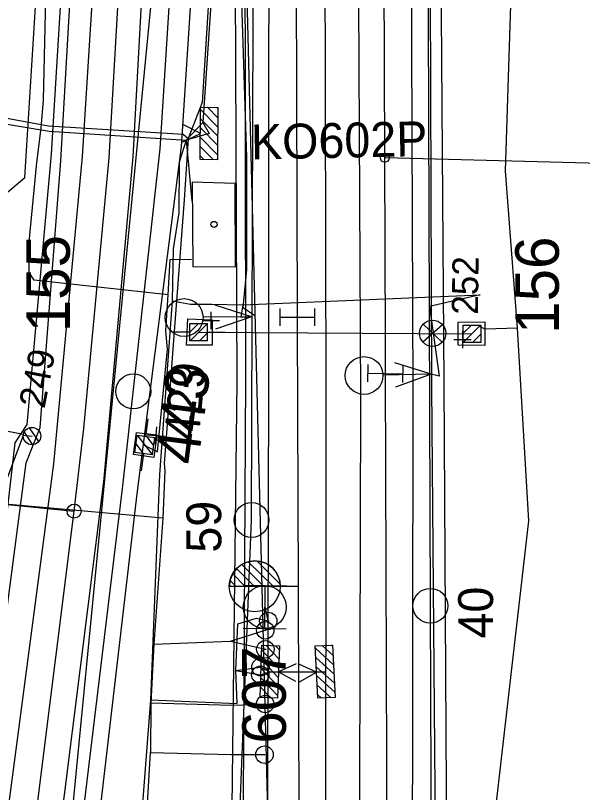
# Model space of a CAD drawing. Extents: x -598638 to -597933, y -1164002 to -1161904.
# Drawn here: x -598261.16 to -598228.67, y -1163238.11 to -1163193.56 of the extents above; entities that cross this region are included whole.
import ezdxf

# ---------------------------------------------------------------- set-up
doc = ezdxf.new("R2010")
doc.units = 0
for name, color, linetype in [('Vrstva 1', 7, 'Continuous'), ('Vrstva 11', 7, 'Continuous'), ('Vrstva 12', 7, 'Continuous'), ('Vrstva 2', 7, 'Continuous'), ('Vrstva 23', 7, 'Continuous'), ('Vrstva 25', 7, 'Continuous'), ('Vrstva 26', 7, 'Continuous'), ('Vrstva 28', 7, 'Continuous'), ('Vrstva 3', 7, 'Continuous'), ('Vrstva 31', 7, 'Continuous'), ('Vrstva 35', 7, 'Continuous'), ('Vrstva 4', 7, 'Continuous'), ('Vrstva 43', 7, 'Continuous'), ('Vrstva 44', 7, 'Continuous'), ('Vrstva 49', 7, 'Continuous'), ('Vrstva 51', 7, 'Continuous'), ('Vrstva 59', 7, 'Continuous'), ('Vrstva 63', 7, 'Continuous'), ('Vrstva 7', 7, 'Continuous')]:
    doc.layers.add(name, color=color, linetype=linetype)

msp = doc.modelspace()

# ---------------------------------------------------------------- linework, layer by layer
at = {"layer": 'Vrstva 1'}
for p, q in [((-598140.033, -1163204.282), (-598240, -1163201.726)), ((-598333.891, -1163214.308), (-598257.805, -1163221.972))]:
    msp.add_line(p, q, dxfattribs=at)
for points in [[(-598239.731, -1163287.87), (-598239.846, -1163247.571), (-598239.957, -1163214.082), (-598239.963, -1163212.175), (-598240, -1163201.726), (-598240.089, -1163175.503), (-598240.169, -1163146.755)], [(-598257.805, -1163221.972), (-598257.251, -1163217.232), (-598255.795, -1163201.726), (-598255.028, -1163188.437), (-598254.941, -1163186.204)], [(-598244.949, -1163226.279), (-598244.999, -1163211.167), (-598245, -1163210.857), (-598245.061, -1163191.702)], [(-598261.135, -1163248.665), (-598260.926, -1163246.987), (-598257.805, -1163221.972)], [(-598244.77, -1163287.888), (-598244.823, -1163269.091), (-598244.89, -1163246.328), (-598244.949, -1163226.279)]]:
    msp.add_lwpolyline(points, dxfattribs=at)
for centre, radius in [((-598240, -1163201.726), 0.25), ((-598257.805, -1163221.972), 0.4)]:
    msp.add_circle(centre, radius, dxfattribs=at)
at = {"layer": 'Vrstva 11'}
for p, q in [((-598251.17, -1163211.714), (-598250.676, -1163211.22)), ((-598251.146, -1163212.22), (-598250.17, -1163211.244)), ((-598235.5, -1163211.777), (-598235.033, -1163211.31)), ((-598235.5, -1163212.307), (-598234.503, -1163211.31)), ((-598251.166, -1163211.721), (-598252.17, -1163211.72)), ((-598250.616, -1163212.22), (-598250.17, -1163211.774)), ((-598250.18, -1163211.721), (-598249.17, -1163211.72)), ((-598234.973, -1163212.31), (-598234.5, -1163211.837)), ((-598253.695, -1163217.694), (-598253.564, -1163216.693)), ((-598253.326, -1163218.717), (-598254.167, -1163217.622)), ((-598253.257, -1163218.192), (-598253.641, -1163217.691)), ((-598253.831, -1163218.675), (-598254.256, -1163218.121)), ((-598253.824, -1163218.672), (-598253.956, -1163219.667))]:
    msp.add_line(p, q, dxfattribs=at)
for points in [[(-598251.17, -1163211.22), (-598250.17, -1163211.22), (-598250.17, -1163212.22), (-598251.17, -1163212.22)], [(-598235.5, -1163211.31), (-598234.5, -1163211.31), (-598234.5, -1163212.31), (-598235.5, -1163212.31)], [(-598254.321, -1163218.61), (-598254.19, -1163217.619), (-598253.199, -1163217.75), (-598253.33, -1163218.741)]]:
    msp.add_lwpolyline(points, close=True, dxfattribs=at)
for points in [[(-598251.17, -1163211.22), (-598250.17, -1163211.22), (-598250.17, -1163212.22), (-598251.17, -1163212.22), (-598251.17, -1163211.22)], [(-598235.5, -1163211.31), (-598234.5, -1163211.31), (-598234.5, -1163212.31), (-598235.5, -1163212.31), (-598235.5, -1163211.31)], [(-598250.67, -1163211.72), (-598235, -1163211.81)], [(-598254.321, -1163218.61), (-598254.19, -1163217.619), (-598253.199, -1163217.75), (-598253.33, -1163218.741), (-598254.321, -1163218.61)]]:
    msp.add_lwpolyline(points, dxfattribs=at)
at = {"layer": 'Vrstva 12'}
for points in [[(-598249.9, -1163211), (-598249.9, -1163212.46), (-598251.36, -1163212.46), (-598251.28, -1163210.95), (-598249.9, -1163211)], [(-598235.79, -1163212.46), (-598235.79, -1163211.14), (-598234.26, -1163211.12), (-598234.27, -1163212.48), (-598235.79, -1163212.46)], [(-598254.4, -1163218.73), (-598254.22, -1163217.46), (-598253.07, -1163217.61), (-598253.24, -1163218.9), (-598254.4, -1163218.73)]]:
    msp.add_lwpolyline(points, dxfattribs=at)
at = {"layer": 'Vrstva 2'}
for p, q in [((-598246.403, -1163226.286), (-598247.82, -1163224.877)), ((-598245.986, -1163226.172), (-598247.332, -1163224.833)), ((-598247.464, -1163226.288), (-598248.488, -1163225.27)), ((-598246.933, -1163226.288), (-598248.193, -1163225.036)), ((-598247.994, -1163226.29), (-598248.714, -1163225.574)), ((-598248.905, -1163226.293), (-598245.978, -1163226.284)), ((-598245.978, -1163226.285), (-598248.905, -1163226.293)), ((-598248.525, -1163226.292), (-598248.863, -1163225.956)), ((-598245.978, -1163226.284), (-598245.978, -1163226.285)), ((-598245.977, -1163226.285), (-598244.949, -1163226.279))]:
    msp.add_line(p, q, dxfattribs=at)
msp.add_lwpolyline([(-598244.823, -1163269.091), (-598244.89, -1163246.328), (-598244.949, -1163226.279)], dxfattribs=at)
msp.add_circle((-598247.449, -1163226.287), 1.462, dxfattribs=at)
msp.add_arc((-598247.441, -1163226.289), 1.464, 0.1882, 180.149, dxfattribs=at)
at = {"layer": 'Vrstva 23'}
for points in [[(-598248.545, -1163207.983), (-598248.577, -1163203.188), (-598251.04, -1163203.118), (-598250.991, -1163207.969)], [(-598248.545, -1163207.983), (-598250.991, -1163207.969)]]:
    msp.add_lwpolyline(points, dxfattribs=at)
at = {"layer": 'Vrstva 25'}
for p, q in [((-598237.825, -1163212.269), (-598236.686, -1163211.282)), ((-598237.796, -1163211.254), (-598236.701, -1163212.292)), ((-598236.5, -1163211.79), (-598235, -1163211.81)), ((-598260.707, -1163217.579), (-598264.145, -1163216.92)), ((-598259.832, -1163217.99), (-598260.369, -1163217.198)), ((-598260.163, -1163218.17), (-598260.656, -1163217.442)), ((-598246.73, -1163228.27), (-598246.63, -1163228.27)), ((-598246.899, -1163228.809), (-598246.799, -1163228.809)), ((-598246.891, -1163229.897), (-598246.791, -1163229.897)), ((-598247.17, -1163230.93), (-598247.07, -1163230.93)), ((-598247.18, -1163231.36), (-598247.08, -1163231.36)), ((-598246.906, -1163233.039), (-598246.806, -1163233.039)), ((-598246.944, -1163235.937), (-598246.844, -1163235.937))]:
    msp.add_line(p, q, dxfattribs=at)
for centre, radius in [((-598237.255, -1163211.776), 0.754), ((-598260.216, -1163217.673), 0.5), ((-598260.216, -1163217.673), 0.5), ((-598246.678, -1163228.27), 0.5), ((-598246.849, -1163228.809), 0.5), ((-598246.841, -1163229.897), 0.5), ((-598247.125, -1163230.923), 0.5), ((-598247.134, -1163231.355), 0.5), ((-598246.856, -1163233.039), 0.5), ((-598246.894, -1163235.937), 0.5)]:
    msp.add_circle(centre, radius, dxfattribs=at)
at = {"layer": 'Vrstva 26'}
for points in [[(-598234.532, -1163246.795), (-598231.747, -1163222.539), (-598232.401, -1163211.481), (-598233.074, -1163202.455), (-598231.426, -1163150.759)], [(-598250.425, -1163175.765), (-598250.438, -1163177.372), (-598249.817, -1163180.408), (-598249.659, -1163185.741), (-598250.466, -1163198.553), (-598251.268, -1163200.601), (-598251.5, -1163204.136), (-598252.635, -1163219.249), (-598252.61, -1163219.663), (-598252.716, -1163222.377)], [(-598250.425, -1163175.765), (-598250.438, -1163177.372), (-598249.817, -1163180.408), (-598249.768, -1163182.028), (-598249.68, -1163185.031), (-598249.659, -1163185.741), (-598249.798, -1163188.008), (-598249.929, -1163190.031), (-598250.466, -1163198.553), (-598251.268, -1163200.601), (-598251.5, -1163204.136)], [(-598247.442, -1163210.772), (-598248.105, -1163210.311), (-598247.898, -1163208.116), (-598247.909, -1163201.707), (-598248.244, -1163191), (-598248.258, -1163177.2), (-598249.088, -1163177.189)], [(-598253.78, -1163218.2), (-598253.02, -1163218.58), (-598252.46, -1163212.69), (-598252.55, -1163211.63), (-598252.42, -1163209.58), (-598260.1, -1163208.74), (-598260.38, -1163208.3), (-598260.4, -1163206.74), (-598259.94, -1163201.98), (-598259.69, -1163200.01), (-598259.55, -1163198.4), (-598259.36, -1163190.06), (-598258.72, -1163189.77), (-598258.7, -1163188.9)], [(-598250.466, -1163198.553), (-598250.466, -1163198.553)], [(-598264.673, -1163198.892), (-598259.279, -1163199.882), (-598251.555, -1163200.359)], [(-598251.555, -1163200.359), (-598251.268, -1163200.601)], [(-598252.42, -1163209.58), (-598252.3, -1163207.55), (-598251.07, -1163207.52)], [(-598232.401, -1163211.481), (-598234.242, -1163211.546), (-598234.568, -1163211.398)], [(-598252.716, -1163222.377), (-598262.19, -1163221.532), (-598260.699, -1163217.627), (-598260.216, -1163217.673)], [(-598252.635, -1163219.249), (-598252.61, -1163219.663), (-598252.716, -1163222.377)], [(-598252.716, -1163222.377), (-598253.236, -1163229.611), (-598253.397, -1163232.966), (-598253.428, -1163235.813)], [(-598253.236, -1163229.611), (-598248.831, -1163229.437), (-598246.849, -1163228.809)], [(-598248.831, -1163229.437), (-598246.841, -1163229.897)], [(-598253.397, -1163232.966), (-598248.765, -1163233.102), (-598246.856, -1163233.039)], [(-598273.816, -1163355.578), (-598271.677, -1163346.374), (-598270.289, -1163341.485), (-598268.518, -1163336.06), (-598265.457, -1163325.157), (-598262.629, -1163312.811), (-598258.667, -1163293.697), (-598257.35, -1163282.225), (-598255.678, -1163268.505), (-598254.603, -1163254.848), (-598253.891, -1163243.597), (-598253.428, -1163235.813)], [(-598253.428, -1163235.813), (-598248.795, -1163235.936), (-598246.894, -1163235.937)]]:
    msp.add_lwpolyline(points, dxfattribs=at)
at = {"layer": 'Vrstva 28'}
for p, q in [((-598249.568, -1163199.954), (-598250.561, -1163198.947)), ((-598249.564, -1163199.424), (-598250.16, -1163198.82)), ((-598249.561, -1163198.894), (-598249.63, -1163198.824)), ((-598249.571, -1163200.485), (-598250.564, -1163199.477)), ((-598249.574, -1163201.014), (-598250.567, -1163200.008)), ((-598249.577, -1163201.544), (-598250.571, -1163200.538)), ((-598249.831, -1163201.821), (-598250.575, -1163201.069)), ((-598250.362, -1163201.818), (-598250.578, -1163201.599)), ((-598246.788, -1163229.673), (-598246.065, -1163230.445)), ((-598246.258, -1163229.69), (-598246.048, -1163229.914)), ((-598242.929, -1163230.785), (-598243.978, -1163229.837)), ((-598242.956, -1163230.256), (-598243.585, -1163229.687)), ((-598242.982, -1163229.727), (-598243.056, -1163229.66)), ((-598247.049, -1163229.943), (-598246.082, -1163230.975)), ((-598247.066, -1163230.473), (-598246.1, -1163231.505)), ((-598242.903, -1163231.316), (-598243.951, -1163230.367)), ((-598247.084, -1163231.002), (-598246.117, -1163232.034)), ((-598242.876, -1163231.845), (-598243.925, -1163230.896)), ((-598247.102, -1163231.533), (-598246.135, -1163232.565)), ((-598242.849, -1163232.374), (-598243.898, -1163231.426)), ((-598247.119, -1163232.063), (-598246.538, -1163232.682)), ((-598243.087, -1163232.666), (-598243.872, -1163231.956)), ((-598243.616, -1163232.692), (-598243.845, -1163232.485)), ((-598247.136, -1163232.592), (-598247.068, -1163232.665))]:
    msp.add_line(p, q, dxfattribs=at)
for points in [[(-598265.34, -1163148.04), (-598265.46, -1163176.63), (-598262, -1163179.28), (-598258.86, -1163182.26), (-598249.45, -1163182.92), (-598249.41, -1163185.89), (-598249.83, -1163190.92), (-598250.42, -1163199.69), (-598251.389, -1163200.707)], [(-598360.628, -1163250.687), (-598347.056, -1163227.008), (-598343.69, -1163221.941), (-598334.357, -1163205.599), (-598329.437, -1163196.714), (-598327.818, -1163196), (-598319.941, -1163195.997), (-598311.197, -1163195.818), (-598297.498, -1163195.446), (-598266.143, -1163199.05), (-598259.229, -1163200.197), (-598251.389, -1163200.707), (-598251.78, -1163201.97), (-598251.81, -1163204.88), (-598252.12, -1163206.93), (-598252.19, -1163209.91), (-598252.91, -1163219.87), (-598253.43, -1163232.8), (-598254.31, -1163244.16)], [(-598250.579, -1163201.818), (-598250.559, -1163198.817), (-598249.56, -1163198.824), (-598249.579, -1163201.824), (-598250.579, -1163201.818)], [(-598251.573, -1163200.81), (-598250.569, -1163200.317), (-598251.566, -1163199.811)], [(-598250.42, -1163199.69), (-598250.07, -1163200.32), (-598251.389, -1163200.707)], [(-598252.19, -1163209.91), (-598251.14, -1163210.1), (-598249.91, -1163210.11), (-598248.14, -1163210.15), (-598234.54, -1163209.58), (-598237.43, -1163210.25), (-598236.88, -1163214.23), (-598237.34, -1163214.12)], [(-598248.14, -1163210.15), (-598248.24, -1163210.86), (-598247.64, -1163210.83)], [(-598253.43, -1163232.8), (-598248.45, -1163233.01), (-598248.54, -1163231.11), (-598248.42, -1163228.44), (-598247.35, -1163228.12), (-598246.68, -1163228.27), (-598246.86, -1163227.47)], [(-598246.041, -1163229.696), (-598246.139, -1163232.695), (-598247.139, -1163232.663), (-598247.04, -1163229.665), (-598246.041, -1163229.696)], [(-598243.834, -1163232.703), (-598243.985, -1163229.707), (-598242.986, -1163229.657), (-598242.835, -1163232.653), (-598243.834, -1163232.703)], [(-598245.074, -1163230.729), (-598246.089, -1163231.196), (-598245.106, -1163231.729)], [(-598248.54, -1163231.11), (-598247.12, -1163230.93), (-598246.59, -1163231.18), (-598243.41, -1163231.18)], [(-598248.54, -1163231.11), (-598247.13, -1163231.36), (-598246.59, -1163231.18)], [(-598244.883, -1163231.755), (-598243.909, -1163231.205), (-598244.933, -1163230.756)]]:
    msp.add_lwpolyline(points, dxfattribs=at)
for points in [[(-598250.579, -1163201.818), (-598250.559, -1163198.817), (-598249.56, -1163198.824), (-598249.579, -1163201.824)], [(-598246.041, -1163229.696), (-598246.139, -1163232.695), (-598247.139, -1163232.663), (-598247.04, -1163229.665)], [(-598243.834, -1163232.703), (-598243.985, -1163229.707), (-598242.986, -1163229.657), (-598242.835, -1163232.653)]]:
    msp.add_lwpolyline(points, close=True, dxfattribs=at)
at = {"layer": 'Vrstva 3'}
for p, q in [((-598247.64, -1163210.83), (-598249.717, -1163210.162)), ((-598245.999, -1163211.36), (-598246.001, -1163210.36)), ((-598243.999, -1163211.354), (-598244.001, -1163210.354)), ((-598247.64, -1163210.83), (-598250.4, -1163210.859)), ((-598247.64, -1163210.83), (-598249.703, -1163211.542)), ((-598246, -1163210.86), (-598244, -1163210.854)), ((-598240.966, -1163214.564), (-598240.948, -1163213.564)), ((-598237.34, -1163214.12), (-598239.426, -1163213.481)), ((-598238.966, -1163214.6), (-598238.948, -1163213.6)), ((-598240.957, -1163214.064), (-598238.957, -1163214.1)), ((-598237.34, -1163214.12), (-598240.099, -1163214.187)), ((-598237.34, -1163214.12), (-598239.393, -1163214.86)), ((-598248.078, -1163226.224), (-598245.614, -1163226.252)), ((-598246.874, -1163228.702), (-598246.846, -1163226.238)), ((-598248.106, -1163228.688), (-598245.642, -1163228.716))]:
    msp.add_line(p, q, dxfattribs=at)
for centre, radius in [((-598251.498, -1163210.875), 1.084), ((-598241.185, -1163214.201), 1.084), ((-598246.874, -1163227.476), 1.232)]:
    msp.add_circle(centre, radius, dxfattribs=at)
at = {"layer": 'Vrstva 31'}
msp.add_lwpolyline([(-598445.119, -1163438.183), (-598442.838, -1163432.572), (-598442.56, -1163432.17), (-598442.26, -1163430.07), (-598433.21, -1163395.711), (-598423.503, -1163370.002), (-598418.049, -1163355.705), (-598405.678, -1163328.228), (-598398.251, -1163314.957), (-598386.091, -1163294.234), (-598371.931, -1163269.732), (-598360.628, -1163250.687), (-598347.056, -1163227.008), (-598343.69, -1163221.941), (-598334.357, -1163205.599), (-598329.437, -1163196.714), (-598327.818, -1163196), (-598319.941, -1163195.997), (-598311.197, -1163195.818), (-598297.498, -1163195.446), (-598266.143, -1163199.05), (-598259.229, -1163200.197), (-598251.389, -1163200.707), (-598251.058, -1163204.207)], dxfattribs=at)
at = {"layer": 'Vrstva 35'}
msp.add_lwpolyline([(-598252.19, -1163209.91), (-598251.14, -1163210.1), (-598249.91, -1163210.11), (-598248.14, -1163210.15), (-598234.54, -1163209.58)], dxfattribs=at)
at = {"layer": 'Vrstva 4'}
for points in [[(-598398.167, -1163553.239), (-598376.487, -1163515.918), (-598348.795, -1163467.979), (-598339.716, -1163452.202), (-598323.266, -1163423.236), (-598308.372, -1163396.471), (-598302.715, -1163384.123), (-598298.324, -1163372.137), (-598289.593, -1163344.221), (-598282.967, -1163321.229), (-598274.797, -1163290.285), (-598269.404, -1163272.781), (-598266.519, -1163258.633), (-598263.896, -1163241.651), (-598261.185, -1163218.05), (-598260.503, -1163217.001), (-598259.092, -1163201.513), (-598258.163, -1163186.176), (-598256.557, -1163141.317), (-598256.485, -1163129.008), (-598255.651, -1163108.451), (-598254.34, -1163087.718), (-598253.319, -1163075.132)], [(-598321.684, -1163563.952), (-598314.649, -1163552.341), (-598302.065, -1163529.781), (-598292.77, -1163512.02), (-598281.731, -1163489.572), (-598274.163, -1163472.668), (-598266.066, -1163452.17), (-598258.953, -1163431.709), (-598252.674, -1163410.241), (-598246.46, -1163386.104), (-598243.144, -1163368.884), (-598239.955, -1163345.756), (-598237.56, -1163323.253), (-598236.679, -1163305.47), (-598236.283, -1163282.744), (-598236.431, -1163244.569), (-598236.596, -1163214.625), (-598236.873, -1163174.881), (-598236.229, -1163131.239), (-598234.781, -1163108.249), (-598234.285, -1163099.455), (-598231.787, -1163078.342)], [(-598283.36, -1163489.15), (-598275.736, -1163471.917), (-598267.551, -1163451.028), (-598260.793, -1163431.262), (-598254.345, -1163409.722), (-598248.47, -1163385.636), (-598245.045, -1163368.352), (-598241.712, -1163345.6), (-598239.462, -1163322.753), (-598238.478, -1163305.467), (-598238.203, -1163283.28), (-598238.406, -1163245.16), (-598238.376, -1163215.168), (-598238.53, -1163175.26), (-598238.394, -1163131.328), (-598237.202, -1163108.683), (-598236.122, -1163097.625), (-598233.737, -1163078.205)], [(-598307.376, -1163503.64), (-598306.256, -1163500.72), (-598304.527, -1163496.743), (-598299.478, -1163486.144), (-598290.117, -1163465.204), (-598280.795, -1163442.724), (-598274.814, -1163425.66), (-598269.09, -1163405.616), (-598262.907, -1163380.487), (-598260.225, -1163366.071), (-598256.638, -1163342.661), (-598254.612, -1163322.432), (-598252.977, -1163304.928), (-598251.437, -1163287.268), (-598250.068, -1163266.224), (-598248.818, -1163245.446), (-598248.467, -1163214.545), (-598248.623, -1163173.63), (-598248.072, -1163131.254), (-598247.596, -1163128.349)], [(-598388.69, -1163572.819), (-598382.701, -1163561.089), (-598361.383, -1163524.292), (-598334.6, -1163477.579), (-598308.353, -1163432.12), (-598292.471, -1163404.257), (-598285.937, -1163390.16), (-598281.631, -1163378.652), (-598277.216, -1163365.008), (-598272.579, -1163348.284), (-598269.387, -1163336.75), (-598267.113, -1163324.869), (-598262.674, -1163291.919), (-598258.642, -1163259.137), (-598254.182, -1163220.99), (-598251.647, -1163201.068), (-598250.766, -1163187.503), (-598249.671, -1163144.519), (-598248.922, -1163130.776), (-598248.69, -1163130.313)]]:
    msp.add_lwpolyline(points, dxfattribs=at)
at = {"layer": 'Vrstva 43'}
for centre in [(-598254.414, -1163215.107), (-598247.635, -1163222.481), (-598237.387, -1163227.403)]:
    msp.add_circle(centre, 1, dxfattribs=at)
at = {"layer": 'Vrstva 44'}
for points in [[(-598295.758, -1163493.483), (-598278.118, -1163452.874), (-598264.209, -1163410.565), (-598254.468, -1163367.19), (-598248.62, -1163321.577), (-598253.497, -1163320.887), (-598249.615, -1163272.581), (-598247.635, -1163222.481), (-598247.486, -1163176.779), (-598247.442, -1163130.148), (-598244.014, -1163084.171), (-598235.33, -1163037.762), (-598224.817, -1163002.559), (-598219.379, -1163002.169), (-598206.652, -1162968.487), (-598191.401, -1162936.053), (-598173.754, -1162904.506), (-598155.689, -1162873.083), (-598136.14, -1162838.446), (-598116.776, -1162804.197)], [(-598286.823, -1163498.793), (-598268.977, -1163457.491), (-598254.684, -1163414.899), (-598244.494, -1163370.7), (-598238.629, -1163323.594), (-598237.183, -1163277.386), (-598237.387, -1163227.403), (-598237.546, -1163176.839), (-598237.218, -1163130.355), (-598233.358, -1163084.011), (-598224.142, -1163038.365), (-598215.269, -1163005.578), (-598224.817, -1163002.559)], [(-598280.199, -1163332.648), (-598271.397, -1163301.809), (-598265.446, -1163302.712), (-598259.208, -1163252.741), (-598251.788, -1163176.385), (-598250.383, -1163130.296), (-598247.948, -1163083.491), (-598241.007, -1163044.927)]]:
    msp.add_lwpolyline(points, dxfattribs=at)
at = {"layer": 'Vrstva 49'}
msp.add_lwpolyline([(-598299.445, -1163361.058), (-598297.068, -1163359.059), (-598293.068, -1163343.621), (-598287.79, -1163320.649), (-598279.637, -1163288.312), (-598274.636, -1163271.434), (-598271.523, -1163257.595), (-598269.283, -1163241.904), (-598267.104, -1163218.072), (-598264.127, -1163206.783), (-598263.144, -1163204.971), (-598260.62, -1163202.843), (-598259.578, -1163186.018), (-598258.253, -1163141.176), (-598259.192, -1163127.718), (-598260.075, -1163119.279), (-598261.182, -1163115.692), (-598261.349, -1163113.122), (-598258.894, -1163101.538), (-598255.65, -1163087.809), (-598254.518, -1163075.132), (-598252.098, -1163061.479), (-598247.841, -1163044.835)], dxfattribs=at)
at = {"layer": 'Vrstva 51'}
for points in [[(-598397.431, -1163553.318), (-598375.745, -1163515.943), (-598348.098, -1163468.333), (-598322.38, -1163423.533), (-598307.542, -1163396.818), (-598301.86, -1163384.541), (-598297.285, -1163372.341), (-598293.283, -1163359.379), (-598288.845, -1163344.448), (-598282.25, -1163321.235), (-598273.825, -1163290.423), (-598265.756, -1163258.778), (-598260.545, -1163219.203), (-598259.744, -1163217.171), (-598258.57, -1163201.891), (-598257.659, -1163186.255), (-598256.038, -1163142.193), (-598255.793, -1163128.623), (-598255.065, -1163108.27), (-598253.781, -1163088.998), (-598252.62, -1163075.466)], [(-598396.078, -1163554.151), (-598374.443, -1163516.599), (-598347.031, -1163469.014), (-598321.218, -1163424.261), (-598306.253, -1163397.723), (-598300.608, -1163385.153), (-598295.814, -1163372.93), (-598291.849, -1163359.988), (-598287.46, -1163344.41), (-598281.154, -1163322.32), (-598272.412, -1163291.197), (-598264.229, -1163259.135), (-598258.972, -1163219.27), (-598257.327, -1163201.644), (-598256.369, -1163186.491), (-598254.79, -1163142.649), (-598254.397, -1163128.629), (-598253.571, -1163108.317), (-598252.585, -1163090.153), (-598250.983, -1163076.012)], [(-598298.888, -1163486.593), (-598289.113, -1163465.583), (-598279.905, -1163442.964), (-598274.107, -1163425.699), (-598268.268, -1163405.757), (-598262.238, -1163380.596), (-598259.701, -1163366.461), (-598255.999, -1163342.847), (-598253.859, -1163322.319), (-598252.407, -1163304.609), (-598250.982, -1163286.31), (-598249.458, -1163266.6), (-598248.128, -1163245.447), (-598247.963, -1163214.31), (-598248.01, -1163173.778), (-598247.475, -1163130.652), (-598247.596, -1163128.349), (-598246.685, -1163112.866), (-598245.177, -1163096.514), (-598242.921, -1163076.624)], [(-598384.985, -1163560.822), (-598363.176, -1163523.063), (-598335.955, -1163475.581), (-598310.179, -1163431.066), (-598295.149, -1163404.135), (-598288.465, -1163389.583), (-598283.96, -1163377.815), (-598279.772, -1163364.473), (-598275.196, -1163348.33), (-598271.933, -1163336.198), (-598269.31, -1163324.265), (-598265.084, -1163292.029), (-598261.053, -1163259.678), (-598256.104, -1163220.296), (-598254.426, -1163201.671), (-598253.667, -1163187.936), (-598252.018, -1163143.494), (-598251.534, -1163128.863), (-598250.791, -1163108.998), (-598250.069, -1163094.383), (-598248.218, -1163076.729)], [(-598305.922, -1163504.285), (-598297.335, -1163487.137), (-598287.92, -1163465.981), (-598279.035, -1163443.103), (-598273.208, -1163425.978), (-598267.2, -1163406.108), (-598261.011, -1163380.887), (-598258.166, -1163366.304), (-598254.569, -1163343.143), (-598252.435, -1163322.084), (-598250.965, -1163305.051), (-598249.488, -1163286.133), (-598247.962, -1163266.793), (-598246.718, -1163245.404), (-598246.637, -1163214.417), (-598246.633, -1163173.748), (-598246.347, -1163129.422), (-598245.484, -1163112.939), (-598244.076, -1163096.672), (-598241.475, -1163076.865)], [(-598389.422, -1163572.47), (-598383.242, -1163561.018), (-598361.933, -1163523.985), (-598335.337, -1163477.363), (-598309.065, -1163431.797), (-598293.626, -1163404.644), (-598286.924, -1163390.082), (-598282.523, -1163378.361), (-598278.252, -1163364.663), (-598273.758, -1163348.557), (-598270.372, -1163336.656), (-598267.892, -1163324.623), (-598263.657, -1163291.858), (-598259.724, -1163259.57), (-598255.007, -1163220.516), (-598252.865, -1163201.196), (-598252.034, -1163187.935), (-598250.643, -1163143.798), (-598250.023, -1163129.244), (-598249.184, -1163109.078), (-598248.423, -1163094.475), (-598246.693, -1163077.089)], [(-598282.309, -1163489.477), (-598274.667, -1163472.413), (-598266.77, -1163451.853), (-598259.621, -1163431.675), (-598253.513, -1163410.04), (-598247.112, -1163385.98), (-598243.846, -1163368.944), (-598240.561, -1163345.639), (-598238.081, -1163322.667), (-598237.343, -1163305.453), (-598236.795, -1163282.909), (-598237.051, -1163244.829), (-598237.298, -1163214.833), (-598237.439, -1163175.203), (-598237.167, -1163131.222), (-598235.767, -1163108.629), (-598234.985, -1163097.818), (-598232.528, -1163078.41)], [(-598244.328, -1163322.203), (-598243.474, -1163305.056), (-598243.331, -1163285.364), (-598243.383, -1163245.466), (-598243.363, -1163215.192), (-598243.435, -1163181.227), (-598242.42, -1163165.706)], [(-598244.328, -1163322.203), (-598242.61, -1163322.308), (-598241.546, -1163305.067), (-598241.263, -1163284.703), (-598241.447, -1163245.468), (-598241.365, -1163215.435), (-598241.552, -1163181.218), (-598241.599, -1163165.738), (-598242.42, -1163165.706)]]:
    msp.add_lwpolyline(points, dxfattribs=at)
at = {"layer": 'Vrstva 59'}
msp.add_circle((-598249.785, -1163205.536), 0.175, dxfattribs=at)
at = {"layer": 'Vrstva 63'}
msp.add_line((-598243.435, -1163367.735), (-598248.331, -1163175.227), dxfattribs=at)
at = {"layer": 'Vrstva 7'}
for p, q in [((-598249.97, -1163210.539), (-598249.97, -1163211.539)), ((-598250.47, -1163211.039), (-598249.47, -1163211.039)), ((-598235.544, -1163211.639), (-598235.544, -1163212.639)), ((-598236.044, -1163212.139), (-598235.044, -1163212.139)), ((-598253.084, -1163217.137), (-598253.16, -1163218.135)), ((-598253.621, -1163217.598), (-598252.623, -1163217.674))]:
    msp.add_line(p, q, dxfattribs=at)

# ---------------------------------------------------------------- texts
at = {"layer": 'Vrstva 11'}
for s, rotation, p in [('155', 90, (-598258.046, -1163211.72)), ('156', 90, (-598230.02, -1163211.81)), ('443', 82.5792, (-598250.703, -1163219.381))]:
    msp.add_text(s, height=2.5, rotation=rotation, dxfattribs=at).set_placement(p)
at = {"layer": 'Vrstva 2'}
msp.add_text('607', height=2.5, rotation=90.1686, dxfattribs=at).set_placement((-598245.662, -1163235.305))
at = {"layer": 'Vrstva 25'}
for s, rotation, p in [('252', 89.2516, (-598234.66, -1163210.719)), ('249', 79.1559, (-598259.502, -1163216.141))]:
    msp.add_text(s, height=1.5, rotation=rotation, dxfattribs=at).set_placement(p)
at = {"layer": 'Vrstva 28'}
msp.add_text('KO602P', height=2, rotation=1.1313, dxfattribs=at).set_placement((-598247.647, -1163201.814))
at = {"layer": 'Vrstva 43'}
for s, rotation, p in [('429', 84.6357, (-598250.668, -1163217.99)), ('59', 90.1896, (-598249.364, -1163224.355)), ('40', 90.1894, (-598233.785, -1163229.277))]:
    msp.add_text(s, height=2, rotation=rotation, dxfattribs=at).set_placement(p)

doc.saveas('drawing.dxf')
